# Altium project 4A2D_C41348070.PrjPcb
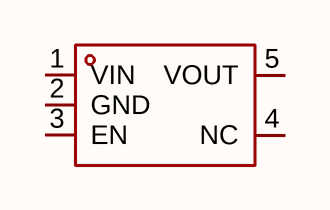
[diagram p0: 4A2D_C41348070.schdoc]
1 sheet, 1 parts. Net scope: global (net labels, ports and power ports of the same name join across sheets).

## Sheet 4A2D_C41348070.schdoc
size 127 x 101 mm

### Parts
U?  4a2d_c41348070  [SOT-23-5_L2.9-W1.6-P0.95-LS2.8-BR_1]  (value not drawn)

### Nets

Not connected (* = marked no-connect by the designer): U? 1(VIN) 2(GND) 3(EN) 4(NC) 5(VOUT)

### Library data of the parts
U? = 4a2d_c41348070: 输出极性:正极;工作电压:5.5V;输出电压:3.3V;输出电流:500mA;电源纹波抑制比(PSRR):70dB@(1kHz);输出类型:固定;; Manufacturer: TECH PUBLIC(台舟); ManufacturerPart: 4A2D; AddInBom: yes; ModelId: 25b054d4db3343b88aee285a0a719589; ModelTransform: 110.236,114.173,0,0,0,0,0.945,-2.44,0; Output Configuration: 正极; Voltage - Supply: 5.5V; Output Voltage: 3.3V; Output Current: 500mA; Voltage Dropout: 200mV@(300mA); standby current: 70uA; Output Type: 固定; Number of Outputs: 1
